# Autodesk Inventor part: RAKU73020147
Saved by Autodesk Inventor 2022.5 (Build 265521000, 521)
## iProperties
Created: 2024-11
Part Number: RAKU73020147
Material: Generic
Description: NOT SPECIFIED
Document SubType Name: Modeling
Designer: AdminForWorker
Density: 1 g/cm^3
Appearance: Default
Title: RAKU73020147
Author: AdminForWorker
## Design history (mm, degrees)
feature "Body1"
body "Solid1"
